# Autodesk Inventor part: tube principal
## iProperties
Created: 2002-06
Part Number: tube principal
Material: Par défaut
Document SubType Name: Modélisation
Designer: REVEST Pierre
Control State: 0
Master: False
Checked Out: False
Shininess: 70.0
Length Units: 11269
Angle Units: 11279
Time Units: 11290
Mass Units: 11283
Length Display Precision: 3
Angle Display Precision: 2
Density: 0.0
Volumn: 0.0
Area: 0.0
PropertySet Name: Model Information
Author: REVEST Pierre
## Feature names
1. Extrusion1
2. Perçage1 [Hole]
3. Perçage2 [Hole]
4. Perçage3 [Hole]
5. Perçage4 [Hole]
6. Extrusion2
7. Extrusion3
8. Congé1 [Fillet]
9. Congé2 [Fillet]
10. Réseau circulaire1 [Circular Pattern]
11. Extrusion5
